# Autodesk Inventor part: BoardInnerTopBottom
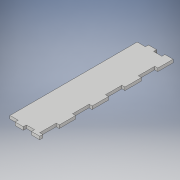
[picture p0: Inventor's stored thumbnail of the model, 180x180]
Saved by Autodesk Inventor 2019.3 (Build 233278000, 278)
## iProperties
Created: 2020-03
Part Number: BoardInnerTopBottom
Material: Generic
Document SubType Name: Modeling
Designer: KrystynWikoff
Density: 1 g/cm^3
Appearance: Default
Author: KrystynWikoff
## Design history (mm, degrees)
sketch "Sketch1"
  geometry: L1 (0, 0)-(25.4, 0); L2 (25.4, 0)-(25.4, -103.1); L3 (25.4, -103.1)-(0, -103.1); L4 (0, -103.1)-(0, 0)
  constraints: 8 end point, 2 parallel, 1 horizontal, 1 perpendicular
  dimensions: "d0" = 25.4 distance of L2.end L3.end; "d1" = 103.1 distance of L1.end L2.end
extrude "Extrusion1" new body sketch "Sketch1" distance "d2" = 2.3622; taper "d3" = 0 deg
sketch "Sketch2" dims "d13" = 25.4, "d23" = 25.4
  geometry: L1 (-6.35, 0)-(-12.7, 0); L2 (-12.7, 0)-(-12.7, 2.362); L3 (-12.7, 2.362)-(-6.35, 2.362); L4 (-6.35, 2.362)-(-6.35, 0); L5 (0, 0)-(0, 103.1) reference; L6 (-25.4, 0)-(0, 0) reference; L7 (-19.05, 0)-(-25.4, 0); L8 (-25.4, 0)-(-25.4, 2.362); L9 (-25.4, 2.362)-(-19.05, 2.362); L10 (-19.05, 2.362)-(-19.05, 0); L11 (0, 103.1)-(-25.4, 103.1) reference; L12 (-6.35, 103.1)-(-12.7, 103.1); L13 (-12.7, 103.1)-(-12.7, 100.738); L14 (-12.7, 100.738)-(-6.35, 100.738); L15 (-6.35, 100.738)-(-6.35, 103.1); L16 (-25.4, 100.738)-(-19.05, 100.738); L17 (-25.4, 103.1)-(-25.4, 100.738); L18 (-19.05, 100.738)-(-19.05, 103.1); L19 (-19.05, 103.1)-(-25.4, 103.1)
  constraints: 32 end point, 4 horizontal, 4 parallel, 2 perpendicular, 1 collinear, 1 point on line, 15 other
  dimensions: "d4" = 2.3622 distance of L3.end L1.start; "d5" = 6.35 distance of L2.end L3.end; "d6" = 6.35 distance between parallel lines of L5 L4; "d7" = 2.3622 distance between parallel lines of L6 L3; "d10" = 12.7 distance of L1.start L7.start; "d15" = 6.35 distance between parallel lines of L5 L15; "d16" = 2.3622 distance of L14.end L12.start; "d17" = 6.35 distance of L13.end L14.end; "d20" = 12.7 distance of L13.end L16.start
extrude "Extrusion2" cut sketch "Sketch2" distance "d25" = 2.3622; taper "d26" = 0 deg
sketch "Sketch3" dims "d35" = 25.4
  geometry: L1 (0, 0)-(0, 103.1) reference; L2 (0, 2.362)-(-2.362, 2.362); L3 (-2.362, 2.362)-(-2.362, 15.062); L4 (-2.362, 15.062)-(0, 15.062); L5 (0, 15.062)-(0, 2.362); L6 (-6.35, 0)-(0, 0) reference; L7 (0, 27.762)-(-2.362, 27.762); L8 (-2.362, 27.762)-(-2.362, 40.462); L9 (-2.362, 40.462)-(0, 40.462); L10 (0, 40.462)-(0, 27.762); L11 (0, 53.162)-(-2.362, 53.162); L12 (-2.362, 53.162)-(-2.362, 65.862); L13 (-2.362, 65.862)-(0, 65.862); L14 (0, 65.862)-(0, 53.162); L15 (0, 78.562)-(-2.362, 78.562); L16 (-2.362, 78.562)-(-2.362, 91.262); L17 (-2.362, 91.262)-(0, 91.262); L18 (0, 91.262)-(0, 78.562)
  constraints: 32 end point, 2 parallel, 1 horizontal, 1 perpendicular, 1 point on line, 1 vertical, 24 other
  dimensions: "d27" = 2.3622 distance of L2.start L2.end; "d28" = 12.7 distance of L2.end L3.end; "d29" = 2.3622 distance between parallel lines of L6 L2; "d32" = 25.4 distance of L2.start L7.start
extrude "Extrusion3" cut sketch "Sketch3" distance "d37" = 2.3622; taper "d38" = 0 deg
body "Solid1"
